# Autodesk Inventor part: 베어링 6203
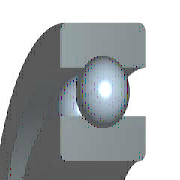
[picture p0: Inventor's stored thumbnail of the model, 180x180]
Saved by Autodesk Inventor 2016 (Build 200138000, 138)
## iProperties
IsCustomPart: 0
Created: 2016-05
Part Number: 베어링 6203
Material: 강, 연강
Description: 깊은 그루브 볼 베어링
Document SubType Name: Modeling
Standard: KS B 2023
Designer: mduedu
Standards Organization: KS
Language: ko-KR
Size Designation: 6203 - 17 x 40 x 12
Categories: <MemberInstance><Categories><Category DisplayName="샤프트 부품" InternalName="7f7aeb1f-a693-4053-b835-cee3144e0d98" Mnemonic="SHFT"><Category DisplayName="베어링" Inter
Density: 1 g/cm^3
Appearance: 노란색
Author: mduedu
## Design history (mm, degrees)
sketch "스케치" dims "d0" = 5.98 (= -0.26 x WD + 0.26 x BD)
  geometry: L1 (3.01, 14.25)-(8.99, 14.25); L2 (6, 14.25)-(6, 11.26); L3 (6, 14.25)-(6, 17.24); L4 (3.778, 12.249)-(0, 12.249); L5 (0, 8.5)-(12, 8.5); L6 (3.778, 16.251)-(0, 16.251); L7 (0, 20)-(12, 20); L8 (12, 8.5)-(12, 12.249); L9 (8.222, 12.249)-(12, 12.249); L10 (8.222, 16.251)-(12, 16.251); L11 (12, 20)-(12, 16.251); L12 (-1.4, 0)-(8.4, 0) reference; L13 (0, -0.3)-(0, 5.3) reference
  constraints: 22 end point, 4 point on line, 2 collinear, 2 perpendicular, 2 symmetric about line, 1 midpoint, 1 parallel, 14 other
  dimensions: "d9" = 17 diameter of L5 L12 (= WD); "d11" = 40 diameter of L7 L12 (= BD); "d12" = 12 distance between parallel lines of L8 L13 (= KB); "d13" = 24.498 diameter of L9 L12 (= 0.326 x BD + 0.674 x WD)
revolve "본체" stored, may be unused: angle "d6" = 90 deg
revolve "볼" stored, may be unused: angle "d7" = 90 deg
pattern_circular "IDS_ARRAYBALL[SIMPL:T]" dims angle "d3" = 360 deg
body "Solid1"
fillet "모깎기1" dims "d1" = 0.6 (= KRS)
other parameters: "WD" = 17 [user parameter; used in 5 equation terms], "BD" = 40 [user parameter; used in 5 equation terms], "KB" = 12 [user parameter; used in 1 equation term], "KRS" = 0.6 [user parameter; used in 1 equation term], "d4" = 0, "d5" = 0, "d8" = 0, "d14" = 0, "d15" = 0, "BBA" = 0 [user parameter], "BC0" = 4750000 [user parameter], "BC" = 9560000 [user parameter], "WR" = 8.5 (= 0.5 x WD) [user parameter]
